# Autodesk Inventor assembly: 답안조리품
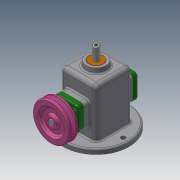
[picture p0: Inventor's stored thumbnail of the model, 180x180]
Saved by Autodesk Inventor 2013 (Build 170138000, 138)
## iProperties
Created: 2021-08
Part Number: 답안조리품
Document SubType Name: Assembly
Designer: a
Author: a
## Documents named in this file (16)
- C:\Users\a\Desktop\710806V1017\답안조리품.iam
- C:\Users\a\Desktop\710806V1017\본체.ipt
- C:\Users\a\Desktop\710806V1017\V벨트풀리.ipt
- C:\Users\a\Desktop\710806V1017\고정핀 1.2x8.ipt
- C:\Users\a\Desktop\710806V1017\뒤커버.ipt
- C:\Users\a\Desktop\710806V1017\링크.ipt
- C:\Users\a\Desktop\710806V1017\멈춤나사 M3x8.ipt
- C:\Users\a\Desktop\710806V1017\베어링 12x32x10.ipt
- C:\Users\a\Desktop\710806V1017\볼트 M4.ipt
- C:\Users\a\Desktop\710806V1017\부시.ipt
- C:\Users\a\Desktop\710806V1017\슬라이드.ipt
- C:\Users\a\Desktop\710806V1017\앞커버.ipt
- C:\Users\a\Desktop\710806V1017\오일 실 12 25 7.ipt
- C:\Users\a\Desktop\710806V1017\키 4x4x10.ipt
- C:\Users\a\Desktop\710806V1017\편심축.ipt
- C:\Users\a\Desktop\710806V1017\핀 5x18.ipt
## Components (3 placed, 3 different names)
1. V벨트풀리:1
2. 고정핀 1.2x8:1
3. 핀 5x18:1
